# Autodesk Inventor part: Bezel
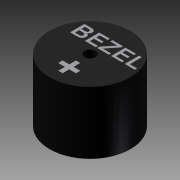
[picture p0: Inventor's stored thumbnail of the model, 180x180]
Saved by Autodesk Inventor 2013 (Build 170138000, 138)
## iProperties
Company: Autodesk Inc.
Created: 2005-12
Part Number: Bezel
Document SubType Name: Modeling
Designer: Autodesk Inc.
Density: 1 g/cm^3
Mass: 0.79218 g
Surface Area: 5.23367 cm^2
Volume: 0.79218 cm^3
Material: Allgemein
Title: Personal Computer
Author: Autodesk Inc.
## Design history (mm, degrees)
sketch "Sketch1"
  geometry: L1 (0, 7.7)-(0, -7.7) reference; L2 (-7.7, 0)-(7.7, 0) reference; C1 r 5.5 at (0, 0)
  constraints: 2 midpoint, 1 centre point
  dimensions: "d0" = 11 diameter of C1
extrude "Extrusion1" new body sketch "Sketch1" distance "d1" = 8.5; taper "d2" = 0 deg
sketch "Sketch2"
  geometry: C1 r 5.5 at (0, 0) reference; C2 r 0.75 at (0, 0)
  constraints: 1 centre point, 1 coincident
  dimensions: "d3" = 1.5 diameter of C2
extrude "Extrusion2" cut sketch "Sketch2" stored distance "d4" = 8.5; taper "d5" = 0 deg
sketch "Sketch3"
  geometry: L1 (-4.162, 3.204)-(11.332, 3.204); L2 (11.332, 3.204)-(11.332, -0.296); L3 (11.332, -0.296)-(-4.162, -0.296); L4 (-4.162, -0.296)-(-4.162, 3.204); L5 (-1.337, -1.694)-(1.517, -1.694); L6 (1.517, -1.694)-(1.517, -4.135); L7 (1.517, -4.135)-(-1.337, -4.135); L8 (-1.337, -4.135)-(-1.337, -1.694)
  constraints: 4 other
extrude "Extrusion3" cut sketch "Sketch3" distance "d6" = 0.05; taper "d7" = 0 deg
body "Solid1"
